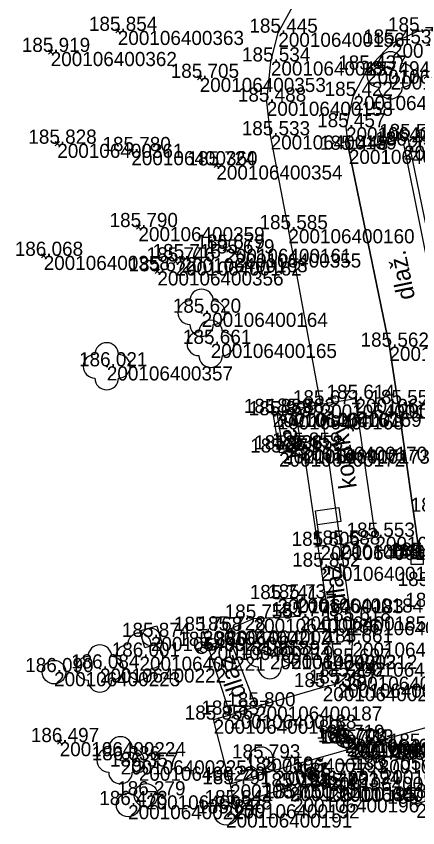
# Model space of a CAD drawing. Extents: x -601392 to -601237, y -1181159 to -1180628.
# Drawn here: x -601307.8 to -601273.7, y -1180962.9 to -1180894 of the extents above; entities that cross this region are included whole.
import ezdxf

# ---------------------------------------------------------------- set-up
doc = ezdxf.new("R2010")
doc.units = 0
for name, color, linetype in [('Definiční bod kú', 7, 'Continuous'), ('Definiční body', 7, 'Continuous'), ('OMP', 7, 'Continuous'), ('Polygon parcely', 7, 'Continuous'), ('Vrstva 16', 7, 'Continuous'), ('Vrstva 17', 7, 'Continuous'), ('Vrstva 36', 7, 'Continuous'), ('Vrstva 37', 7, 'Continuous'), ('Vrstva 41', 7, 'Continuous'), ('Vrstva 43', 7, 'Continuous'), ('Vrstva 49', 7, 'Continuous'), ('Vrstva 61', 7, 'Continuous')]:
    doc.layers.add(name, color=color, linetype=linetype)

msp = doc.modelspace()

# ---------------------------------------------------------------- linework, layer by layer
at = {"layer": 'Definiční bod kú'}
for points in [[(-601285.624, -1180927.879), (-601284.107, -1180927.658), (-601283.639, -1180930.538), (-601285.161, -1180930.769), (-601285.624, -1180927.879)], [(-601273.854, -1180960.812), (-601272.313, -1180960.338), (-601268.424, -1180959.145), (-601258.861, -1180955.933)]]:
    msp.add_lwpolyline(points, dxfattribs=at)
at = {"layer": 'Definiční body'}
for p, q in [((-601276.1, -1180899.057), (-601275.958, -1180899.057)), ((-601292.142, -1180919.183), (-601292, -1180919.183)), ((-601291.371, -1180921.821), (-601291.229, -1180921.821)), ((-601300.192, -1180923.728), (-601300.05, -1180923.728)), ((-601286.349, -1180948.212), (-601286.207, -1180948.212)), ((-601297.42, -1180948.342), (-601297.278, -1180948.342)), ((-601300.777, -1180949.343), (-601300.635, -1180949.343)), ((-601299.023, -1180957.132), (-601298.881, -1180957.132))]:
    msp.add_line(p, q, dxfattribs=at)
for centre, start, end in [((-601276.04, -1180898.055), 0, 180), ((-601277.04, -1180899.055), 90, 270), ((-601275.04, -1180899.055), 270, 90), ((-601276.04, -1180900.055), 180, 0), ((-601292.082, -1180918.181), 0, 180), ((-601293.082, -1180919.181), 90, 270), ((-601291.082, -1180919.181), 270, 90), ((-601291.311, -1180920.819), 0, 180), ((-601292.082, -1180920.181), 180, 0), ((-601292.311, -1180921.819), 90, 270), ((-601290.311, -1180921.819), 270, 90), ((-601300.132, -1180922.726), 0, 180), ((-601301.132, -1180923.726), 90, 270), ((-601299.132, -1180923.726), 270, 90), ((-601291.311, -1180922.819), 180, 0), ((-601300.132, -1180924.726), 180, 0), ((-601286.289, -1180947.21), 0, 180), ((-601297.36, -1180947.34), 0, 180), ((-601300.717, -1180948.341), 0, 180), ((-601298.36, -1180948.34), 90, 270), ((-601296.36, -1180948.34), 270, 90), ((-601287.289, -1180948.21), 90, 270), ((-601285.289, -1180948.21), 270, 90), ((-601301.717, -1180949.341), 90, 270), ((-601299.717, -1180949.341), 270, 90), ((-601297.36, -1180949.34), 180, 0), ((-601286.289, -1180949.21), 180, 0), ((-601300.717, -1180950.341), 180, 0), ((-601298.963, -1180956.13), 0, 180), ((-601299.963, -1180957.13), 90, 270), ((-601297.963, -1180957.13), 270, 90), ((-601298.963, -1180958.13), 180, 0)]:
    msp.add_arc(centre, 1, start, end, dxfattribs=at)
at = {"layer": 'OMP'}
for p, q in [((-601299.191, -1180895.283), (-601299.191, -1180895.283)), ((-601285.564, -1180895.44), (-601285.564, -1180895.44)), ((-601273.804, -1180895.333), (-601273.804, -1180895.333)), ((-601275.916, -1180896.367), (-601275.916, -1180896.367)), ((-601304.886, -1180897.072), (-601304.886, -1180897.072)), ((-601286.196, -1180897.88), (-601286.196, -1180897.88)), ((-601278.025, -1180898.568), (-601278.025, -1180898.568)), ((-601292.242, -1180899.269), (-601292.242, -1180899.269)), ((-601276.029, -1180899.057), (-601276.029, -1180899.057)), ((-601279.186, -1180900.804), (-601279.186, -1180900.804)), ((-601286.544, -1180901.289), (-601286.544, -1180901.289)), ((-601279.819, -1180903.453), (-601279.819, -1180903.453)), ((-601286.216, -1180904.141), (-601286.216, -1180904.141)), ((-601304.329, -1180904.853), (-601304.329, -1180904.853)), ((-601274.554, -1180904.375), (-601274.554, -1180904.375)), ((-601298.041, -1180905.478), (-601298.041, -1180905.478)), ((-601279.576, -1180905.367), (-601279.576, -1180905.367)), ((-601274.889, -1180905.013), (-601274.889, -1180905.013)), ((-601290.824, -1180906.694), (-601290.824, -1180906.694)), ((-601297.437, -1180911.921), (-601297.437, -1180911.921)), ((-601284.707, -1180912.099), (-601284.707, -1180912.099)), ((-601290.06, -1180913.76), (-601290.06, -1180913.76)), ((-601305.483, -1180914.36), (-601305.483, -1180914.36)), ((-601293.781, -1180914.555), (-601293.781, -1180914.555)), ((-601289.238, -1180914.155), (-601289.238, -1180914.155)), ((-601294.291, -1180914.835), (-601294.291, -1180914.835)), ((-601295.829, -1180915.673), (-601295.829, -1180915.673)), ((-601292.071, -1180919.183), (-601292.071, -1180919.183)), ((-601291.3, -1180921.821), (-601291.3, -1180921.821)), ((-601276.135, -1180922.063), (-601276.135, -1180922.063)), ((-601300.121, -1180923.728), (-601300.121, -1180923.728)), ((-601281.97, -1180926.952), (-601281.97, -1180926.952)), ((-601279.021, -1180926.482), (-601279.021, -1180926.482)), ((-601275.392, -1180926.93), (-601275.392, -1180926.93)), ((-601286.039, -1180927.685), (-601286.039, -1180927.685)), ((-601285.624, -1180927.879), (-601285.624, -1180927.879)), ((-601284.107, -1180927.658), (-601284.107, -1180927.658)), ((-601285.5, -1180931.036), (-601285.5, -1180931.036)), ((-601285.161, -1180930.769), (-601285.161, -1180930.769)), ((-601283.639, -1180930.538), (-601283.639, -1180930.538)), ((-601283.414, -1180930.782), (-601283.414, -1180930.782)), ((-601277.324, -1180938.176), (-601277.324, -1180938.176)), ((-601281.981, -1180938.949), (-601281.981, -1180938.949)), ((-601280.252, -1180938.84), (-601280.252, -1180938.84)), ((-601273.778, -1180940.019), (-601273.778, -1180940.019)), ((-601281.947, -1180940.716), (-601281.947, -1180940.716)), ((-601285.633, -1180943.465), (-601285.633, -1180943.465)), ((-601283.975, -1180943.404), (-601283.975, -1180943.404)), ((-601287.662, -1180945.119), (-601287.662, -1180945.119)), ((-601283.724, -1180944.923), (-601283.724, -1180944.923)), ((-601279.348, -1180945.327), (-601279.348, -1180945.327)), ((-601291.97, -1180946.156), (-601291.97, -1180946.156)), ((-601289.972, -1180946.121), (-601289.972, -1180946.121)), ((-601296.384, -1180946.67), (-601296.384, -1180946.67)), ((-601291.603, -1180947.429), (-601291.603, -1180947.429)), ((-601279.276, -1180947.148), (-601279.276, -1180947.148)), ((-601286.278, -1180948.212), (-601286.278, -1180948.212)), ((-601284.472, -1180948.187), (-601284.472, -1180948.187)), ((-601297.349, -1180948.342), (-601297.349, -1180948.342)), ((-601279.382, -1180948.845), (-601279.382, -1180948.845)), ((-601304.598, -1180949.655), (-601304.598, -1180949.655)), ((-601300.706, -1180949.343), (-601300.706, -1180949.343)), ((-601279.806, -1180950.031), (-601279.806, -1180950.031)), ((-601281.788, -1180950.921), (-601281.788, -1180950.921)), ((-601280.526, -1180950.625), (-601280.526, -1180950.625)), ((-601287.451, -1180952.557), (-601287.451, -1180952.557)), ((-601291.058, -1180953.679), (-601291.058, -1180953.679)), ((-601289.646, -1180953.262), (-601289.646, -1180953.262)), ((-601304.123, -1180955.586), (-601304.123, -1180955.586)), ((-601279.897, -1180955.308), (-601279.897, -1180955.308)), ((-601279.766, -1180955.601), (-601279.766, -1180955.601)), ((-601279.541, -1180955.717), (-601279.541, -1180955.717)), ((-601279.131, -1180955.706), (-601279.131, -1180955.706)), ((-601273.728, -1180956.062), (-601273.728, -1180956.062)), ((-601298.952, -1180957.132), (-601298.952, -1180957.132)), ((-601287.041, -1180956.976), (-601287.041, -1180956.976)), ((-601277.035, -1180957.068), (-601277.035, -1180957.068)), ((-601297.401, -1180957.663), (-601297.401, -1180957.663)), ((-601285.912, -1180958.009), (-601285.912, -1180958.009)), ((-601281.301, -1180958.529), (-601281.301, -1180958.529)), ((-601276.772, -1180957.948), (-601276.772, -1180957.948)), ((-601289.659, -1180959.164), (-601289.659, -1180959.164)), ((-601284.583, -1180959.401), (-601284.583, -1180959.401)), ((-601281.272, -1180959.453), (-601281.272, -1180959.453)), ((-601280.366, -1180959.402), (-601280.366, -1180959.402)), ((-601296.791, -1180960.1), (-601296.791, -1180960.1)), ((-601284.319, -1180960.348), (-601284.319, -1180960.348)), ((-601298.312, -1180960.925), (-601298.312, -1180960.925)), ((-601289.377, -1180960.857), (-601289.377, -1180960.857)), ((-601273.854, -1180960.812), (-601273.854, -1180960.812)), ((-601289.997, -1180961.634), (-601289.997, -1180961.634))]:
    msp.add_line(p, q, dxfattribs=at)
at = {"layer": 'Polygon parcely'}
msp.add_line((-601282.476, -1180939.022), (-601281.486, -1180938.876), dxfattribs=at)
msp.add_lwpolyline([(-601281.981, -1180938.949), (-601282.419, -1180935.981), (-601280.441, -1180935.689), (-601280.265, -1180936.876), (-601282.244, -1180937.168)], dxfattribs=at)
at = {"layer": 'Vrstva 16'}
msp.add_line((-601291.97, -1180946.156), (-601289.646, -1180953.262), dxfattribs=at)
for points in [[(-601249.754, -1180947.471), (-601265.789, -1180952.096), (-601269.852, -1180953.465), (-601285.912, -1180958.009), (-601289.659, -1180959.164), (-601291.058, -1180953.679), (-601289.646, -1180953.262), (-601287.451, -1180952.557), (-601281.788, -1180950.921), (-601280.526, -1180950.625), (-601279.806, -1180950.031), (-601279.382, -1180948.845), (-601279.276, -1180947.148), (-601279.348, -1180945.327), (-601280.252, -1180938.84), (-601277.324, -1180938.176), (-601279.021, -1180926.482), (-601281.97, -1180926.952), (-601284.707, -1180912.099), (-601286.216, -1180904.141), (-601286.544, -1180901.289), (-601286.196, -1180897.88), (-601285.564, -1180895.44), (-601284.062, -1180892.694)], [(-601273.56, -1180939.874), (-601275.392, -1180926.93), (-601276.135, -1180922.063), (-601279.576, -1180905.367), (-601279.819, -1180903.453), (-601279.186, -1180900.804), (-601278.025, -1180898.568), (-601275.916, -1180896.367), (-601273.804, -1180895.333), (-601271.231, -1180895.02)], [(-601270.846, -1180922.356), (-601274.554, -1180904.375), (-601279.576, -1180905.367), (-601276.135, -1180922.063), (-601275.392, -1180926.93), (-601273.56, -1180939.874)], [(-601281.97, -1180926.952), (-601286.039, -1180927.685), (-601285.5, -1180931.036), (-601283.414, -1180930.782), (-601281.947, -1180940.716), (-601280.526, -1180950.625), (-601279.806, -1180950.031), (-601279.382, -1180948.845), (-601279.276, -1180947.148), (-601279.348, -1180945.327), (-601280.252, -1180938.84), (-601281.97, -1180926.952)], [(-601280.252, -1180938.84), (-601277.324, -1180938.176), (-601279.021, -1180926.482), (-601281.97, -1180926.952)], [(-601287.451, -1180952.557), (-601289.972, -1180946.121), (-601287.662, -1180945.119), (-601283.724, -1180944.923), (-601283.975, -1180943.404), (-601285.633, -1180943.465)], [(-601249.754, -1180947.471), (-601265.789, -1180952.096), (-601269.852, -1180953.465), (-601285.912, -1180958.009), (-601289.659, -1180959.164), (-601289.377, -1180960.857), (-601284.583, -1180959.401), (-601284.319, -1180960.348)], [(-601247.46, -1180948.339), (-601255.228, -1180950.689), (-601253.62, -1180954.356), (-601258.861, -1180955.933), (-601260.043, -1180952.057), (-601265.542, -1180953.692), (-601269.798, -1180955.071), (-601268.424, -1180959.145), (-601272.313, -1180960.338), (-601273.312, -1180957.086), (-601273.728, -1180956.062), (-601277.035, -1180957.068), (-601276.772, -1180957.948)], [(-601281.272, -1180959.453), (-601281.301, -1180958.529), (-601280.366, -1180959.402)]]:
    msp.add_lwpolyline(points, dxfattribs=at)
at = {"layer": 'Vrstva 17'}
msp.add_line((-601271.349, -1180922.638), (-601274.889, -1180905.013), dxfattribs=at)
at = {"layer": 'Vrstva 36'}
for p, q in [((-601292.564, -1180947.707), (-601291.603, -1180947.429)), ((-601291.618, -1180947.75), (-601291.994, -1180947.542)), ((-601290.642, -1180947.151), (-601291.603, -1180947.429)), ((-601291.42, -1180947.692), (-601291.212, -1180947.316)), ((-601291.041, -1180947.784), (-601290.662, -1180947.095)), ((-601291.889, -1180948.029), (-601292.503, -1180947.689))]:
    msp.add_line(p, q, dxfattribs=at)
for centre in [(-601291.123, -1180947.29), (-601292.083, -1180947.568)]:
    msp.add_circle(centre, 0.5, dxfattribs=at)
for centre in [(-601292.083, -1180947.568), (-601291.123, -1180947.29)]:
    msp.add_arc(centre, 0.5, 196.11363, 16.11363, dxfattribs=at)
at = {"layer": 'Vrstva 37'}
msp.add_lwpolyline([(-601297.313, -1180946.158), (-601295.872, -1180945.741), (-601295.455, -1180947.182), (-601296.896, -1180947.599), (-601297.313, -1180946.158)], dxfattribs=at)
msp.add_circle((-601296.384, -1180946.67), 0.75, dxfattribs=at)
at = {"layer": 'Vrstva 41'}
for p, q in [((-601282.741, -1180947.6), (-601282.691, -1180948.599)), ((-601282.716, -1180948.1), (-601283.723, -1180948.15)), ((-601280.857, -1180953.752), (-601279.895, -1180953.479)), ((-601280.376, -1180953.615), (-601280.101, -1180954.585)), ((-601280.263, -1180955.964), (-601279.53, -1180954.653))]:
    msp.add_line(p, q, dxfattribs=at)
for centre, radius in [((-601284.472, -1180948.187), 0.75), ((-601279.897, -1180955.308), 0.75), ((-601279.766, -1180955.601), 0.5), ((-601279.541, -1180955.717), 0.5), ((-601279.131, -1180955.706), 0.5), ((-601297.401, -1180957.663), 0.5)]:
    msp.add_circle(centre, radius, dxfattribs=at)
at = {"layer": 'Vrstva 43'}
msp.add_lwpolyline([(-601274.278, -1180940.019), (-601274.278, -1180939.519), (-601273.278, -1180939.519), (-601273.278, -1180940.519), (-601274.278, -1180940.519), (-601274.278, -1180940.019), (-601273.278, -1180940.019)], dxfattribs=at)
for centre in [(-601304.598, -1180949.655), (-601287.041, -1180956.976), (-601296.791, -1180960.1), (-601298.312, -1180960.925), (-601289.997, -1180961.634)]:
    msp.add_circle(centre, 1, dxfattribs=at)
at = {"layer": 'Vrstva 49'}
for p, q in [((-601299.368, -1180895.106), (-601299.014, -1180895.46)), ((-601299.368, -1180895.46), (-601299.014, -1180895.106)), ((-601305.063, -1180896.895), (-601304.709, -1180897.249)), ((-601305.063, -1180897.249), (-601304.709, -1180896.895)), ((-601292.419, -1180899.092), (-601292.065, -1180899.446)), ((-601292.419, -1180899.446), (-601292.065, -1180899.092)), ((-601304.506, -1180904.676), (-601304.152, -1180905.03)), ((-601304.506, -1180905.03), (-601304.152, -1180904.676)), ((-601298.218, -1180905.301), (-601297.864, -1180905.655)), ((-601298.218, -1180905.655), (-601297.864, -1180905.301)), ((-601291.001, -1180906.517), (-601290.647, -1180906.871)), ((-601291.001, -1180906.871), (-601290.647, -1180906.517)), ((-601297.614, -1180911.744), (-601297.26, -1180912.098)), ((-601297.614, -1180912.098), (-601297.26, -1180911.744)), ((-601290.237, -1180913.583), (-601289.883, -1180913.937)), ((-601290.237, -1180913.937), (-601289.883, -1180913.583)), ((-601305.66, -1180914.183), (-601305.306, -1180914.537)), ((-601305.66, -1180914.537), (-601305.306, -1180914.183)), ((-601293.958, -1180914.378), (-601293.604, -1180914.732)), ((-601293.958, -1180914.732), (-601293.604, -1180914.378)), ((-601289.415, -1180913.978), (-601289.061, -1180914.332)), ((-601289.415, -1180914.332), (-601289.061, -1180913.978)), ((-601294.468, -1180914.658), (-601294.114, -1180915.012)), ((-601294.468, -1180915.012), (-601294.114, -1180914.658)), ((-601296.006, -1180915.496), (-601295.652, -1180915.85)), ((-601296.006, -1180915.85), (-601295.652, -1180915.496)), ((-601304.3, -1180955.409), (-601303.946, -1180955.763)), ((-601304.3, -1180955.763), (-601303.946, -1180955.409))]:
    msp.add_line(p, q, dxfattribs=at)

# ---------------------------------------------------------------- texts
at = {"layer": 'Definiční bod kú'}
msp.add_text('zast.', height=1.5, rotation=279.22989, dxfattribs=at).set_placement((-601285.366, -1180928.1))
at = {"layer": 'OMP'}
for s, p in [('200106400363', (-601299.191, -1180896.483)), ('200106400156', (-601285.564, -1180896.64)), ('200106400321', (-601275.916, -1180897.567)), ('200106400362', (-601304.886, -1180898.272)), ('200106400157', (-601286.196, -1180899.08)), ('200106400299', (-601278.025, -1180899.768)), ('200106400353', (-601292.242, -1180900.469)), ('200106400300', (-601276.029, -1180900.257)), ('200106400298', (-601279.186, -1180902.004)), ('200106400158', (-601286.544, -1180902.489)), ('200106400297', (-601279.819, -1180904.653)), ('200106400159', (-601286.216, -1180905.341)), ('200106400361', (-601304.329, -1180906.053)), ('200106400294', (-601274.554, -1180905.575)), ('200106400360', (-601298.041, -1180906.678)), ('200106400296', (-601279.576, -1180906.567)), ('200106400293', (-601274.889, -1180906.213)), ('200106400354', (-601290.824, -1180907.894)), ('200106400359', (-601297.437, -1180913.121)), ('200106400160', (-601284.707, -1180913.299)), ('200106400161', (-601290.06, -1180914.96)), ('200106400358', (-601305.483, -1180915.56)), ('200106400163', (-601293.781, -1180915.755)), ('200106400355', (-601289.238, -1180915.355)), ('200106400162', (-601294.291, -1180916.035)), ('200106400356', (-601295.829, -1180916.873)), ('200106400164', (-601292.071, -1180920.383)), ('200106400165', (-601291.3, -1180923.021)), ('200106400290', (-601276.135, -1180923.263)), ('200106400357', (-601300.121, -1180924.928)), ('200106400175', (-601281.97, -1180928.152)), ('200106400176', (-601279.021, -1180927.682)), ('200106400289', (-601275.392, -1180928.13)), ('200106400169', (-601284.107, -1180928.858)), ('200106400167', (-601286.039, -1180928.885)), ('200106400168', (-601285.624, -1180929.079)), ('200106400172', (-601285.5, -1180932.236)), ('200106400171', (-601285.161, -1180931.969)), ('200106400170', (-601283.639, -1180931.738)), ('200106400173', (-601283.414, -1180931.982)), ('200106400177', (-601277.324, -1180939.376)), ('200106400179', (-601281.981, -1180940.149)), ('200106400178', (-601280.252, -1180940.04)), ('200106400181', (-601281.947, -1180941.916)), ('200106400183', (-601285.633, -1180944.665)), ('200106400184', (-601283.975, -1180944.604)), ('200106400186', (-601287.662, -1180946.319)), ('200106400185', (-601283.724, -1180946.123)), ('200106400211', (-601279.348, -1180946.527)), ('200106400217', (-601291.97, -1180947.356)), ('200106400214', (-601289.972, -1180947.321)), ('200106400220', (-601296.384, -1180947.87)), ('200106400219', (-601291.603, -1180948.629)), ('200106400210', (-601279.276, -1180948.348)), ('200106400213', (-601286.278, -1180949.412)), ('200106400212', (-601284.472, -1180949.387)), ('200106400221', (-601297.349, -1180949.542)), ('200106400209', (-601279.382, -1180950.045)), ('200106400223', (-601304.598, -1180950.855)), ('200106400222', (-601300.706, -1180950.543)), ('200106400208', (-601279.806, -1180951.231)), ('200106400207', (-601281.788, -1180952.121)), ('200106400206', (-601280.526, -1180951.825)), ('200106400187', (-601287.451, -1180953.757)), ('200106400189', (-601291.058, -1180954.879)), ('200106400188', (-601289.646, -1180954.462)), ('200106400224', (-601304.123, -1180956.786)), ('200106400229', (-601279.897, -1180956.508)), ('200106400230', (-601279.766, -1180956.801)), ('200106400231', (-601279.541, -1180956.917)), ('200106400232', (-601279.131, -1180956.906)), ('200106400225', (-601298.952, -1180958.332)), ('200106400193', (-601287.041, -1180958.176)), ('200106400200', (-601277.035, -1180958.268)), ('200106400226', (-601297.401, -1180958.863)), ('200106400194', (-601285.912, -1180959.209)), ('200106400198', (-601281.301, -1180959.729)), ('200106400203', (-601276.772, -1180959.148)), ('200106400190', (-601289.659, -1180960.364)), ('200106400195', (-601284.583, -1180960.601)), ('200106400197', (-601281.272, -1180960.653)), ('200106400199', (-601280.366, -1180960.602)), ('200106400228', (-601296.791, -1180961.3)), ('200106400196', (-601284.319, -1180961.548)), ('200106400227', (-601298.312, -1180962.125)), ('200106400192', (-601289.377, -1180962.057)), ('200106400233', (-601273.854, -1180962.012)), ('200106400191', (-601289.997, -1180962.834))]:
    msp.add_text(s, height=1.2, dxfattribs=at).set_placement(p)
at = {"layer": 'Vrstva 16'}
for s, rotation, p in [('dlaž.', 101.64545, (-601273.944, -1180917.935)), ('kostky', 98.25696, (-601278.899, -1180933.998)), ('dlaž.', 98.2232, (-601279.771, -1180943.995)), ('dlaž.', 108.11021, (-601288.278, -1180951.584)), ('dlaž.', 16.89422, (-601284.583, -1180959.401))]:
    msp.add_text(s, height=1.5, rotation=rotation, dxfattribs=at).set_placement(p)
at = {"layer": 'Vrstva 61'}
for s, p in [('185.854', (-601301.642, -1180895.283)), ('185.445', (-601288.02, -1180895.44)), ('185.460', (-601276.255, -1180895.333)), ('185.453', (-601278.368, -1180896.367)), ('185.919', (-601307.34, -1180897.072)), ('185.534', (-601288.647, -1180897.88)), ('185.437', (-601280.477, -1180898.568)), ('185.705', (-601294.698, -1180899.269)), ('185.494', (-601278.48, -1180899.057)), ('185.488', (-601288.998, -1180901.289)), ('185.422', (-601281.634, -1180900.804)), ('185.457', (-601282.271, -1180903.453)), ('185.533', (-601288.668, -1180904.141)), ('185.506', (-601277.006, -1180904.375)), ('185.828', (-601306.783, -1180904.853)), ('185.448', (-601282.03, -1180905.367)), ('186.497', (-601277.341, -1180905.013)), ('185.780', (-601300.492, -1180905.478)), ('185.724', (-601293.275, -1180906.694)), ('185.790', (-601299.888, -1180911.921)), ('185.585', (-601287.163, -1180912.099)), ('186.068', (-601307.937, -1180914.36)), ('185.679', (-601292.514, -1180913.76)), ('185.679', (-601291.692, -1180914.155)), ('185.746', (-601296.743, -1180914.835)), ('185.715', (-601296.237, -1180914.555)), ('185.672', (-601298.277, -1180915.673)), ('185.620', (-601294.522, -1180919.183)), ('185.661', (-601293.657, -1180921.821)), ('185.562', (-601278.583, -1180922.063)), ('186.021', (-601302.478, -1180923.728)), ('185.614', (-601281.472, -1180926.482)), ('185.671', (-601284.327, -1180926.952)), ('185.551', (-601277.749, -1180926.93)), ('185.889', (-601288.493, -1180927.685)), ('185.899', (-601288.078, -1180927.879)), ('185.883', (-601286.559, -1180927.658)), ('185.836', (-601287.613, -1180930.769)), ('185.859', (-601286.093, -1180930.538)), ('185.858', (-601285.868, -1180930.782)), ('185.873', (-601287.952, -1180931.036)), ('185.643', (-601274.325, -1180936.055)), ('185.553', (-601279.776, -1180938.176)), ('185.806', (-601284.433, -1180938.949)), ('185.588', (-601282.706, -1180938.84)), ('185.446', (-601276.012, -1180939.874)), ('185.436', (-601276.23, -1180940.019)), ('185.852', (-601284.395, -1180940.716)), ('185.493', (-601275.436, -1180942.353)), ('185.741', (-601287.99, -1180943.465)), ('185.734', (-601286.426, -1180943.404)), ('185.515', (-601274.784, -1180944.122)), ('185.755', (-601290.118, -1180945.119)), ('185.773', (-601286.176, -1180944.923)), ('185.618', (-601281.802, -1180945.327)), ('185.874', (-601298.835, -1180946.67)), ('185.768', (-601294.424, -1180946.156)), ('185.728', (-601292.426, -1180946.121)), ('185.866', (-601294.055, -1180947.429)), ('185.661', (-601281.633, -1180947.148)), ('186.001', (-601299.706, -1180948.342)), ('185.818', (-601288.732, -1180948.212)), ('185.792', (-601286.92, -1180948.187)), ('186.084', (-601303.157, -1180949.343)), ('185.697', (-601281.834, -1180948.845)), ('186.090', (-601307.049, -1180949.655)), ('185.742', (-601282.254, -1180950.031)), ('185.757', (-601282.978, -1180950.625)), ('185.738', (-601284.242, -1180950.921)), ('185.800', (-601289.902, -1180952.557)), ('185.837', (-601292.098, -1180953.262)), ('185.856', (-601293.51, -1180953.679)), ('186.497', (-601306.575, -1180955.586)), ('185.719', (-601282.351, -1180955.308)), ('185.703', (-601282.218, -1180955.601)), ('185.724', (-601281.992, -1180955.717)), ('185.713', (-601281.583, -1180955.706)), ('185.799', (-601276.182, -1180956.062)), ('185.793', (-601289.493, -1180956.976)), ('185.786', (-601279.487, -1180957.068)), ('186.336', (-601301.404, -1180957.132)), ('186.357', (-601299.853, -1180957.663)), ('185.764', (-601275.763, -1180957.086)), ('185.759', (-601288.366, -1180958.009)), ('185.705', (-601279.228, -1180957.948)), ('185.777', (-601283.753, -1180958.529)), ('185.791', (-601292.016, -1180959.164)), ('185.794', (-601287.034, -1180959.401)), ('185.745', (-601283.728, -1180959.453)), ('185.723', (-601282.818, -1180959.402)), ('186.279', (-601299.245, -1180960.1)), ('185.750', (-601286.77, -1180960.348)), ('185.647', (-601274.765, -1180960.338)), ('186.473', (-601300.764, -1180960.925)), ('185.844', (-601291.828, -1180960.857)), ('185.489', (-601276.308, -1180960.812)), ('185.846', (-601292.449, -1180961.634))]:
    msp.add_text(s, height=1.2, dxfattribs=at).set_placement(p)

doc.saveas('drawing.dxf')
